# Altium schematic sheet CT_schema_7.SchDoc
size 301 x 247 mm
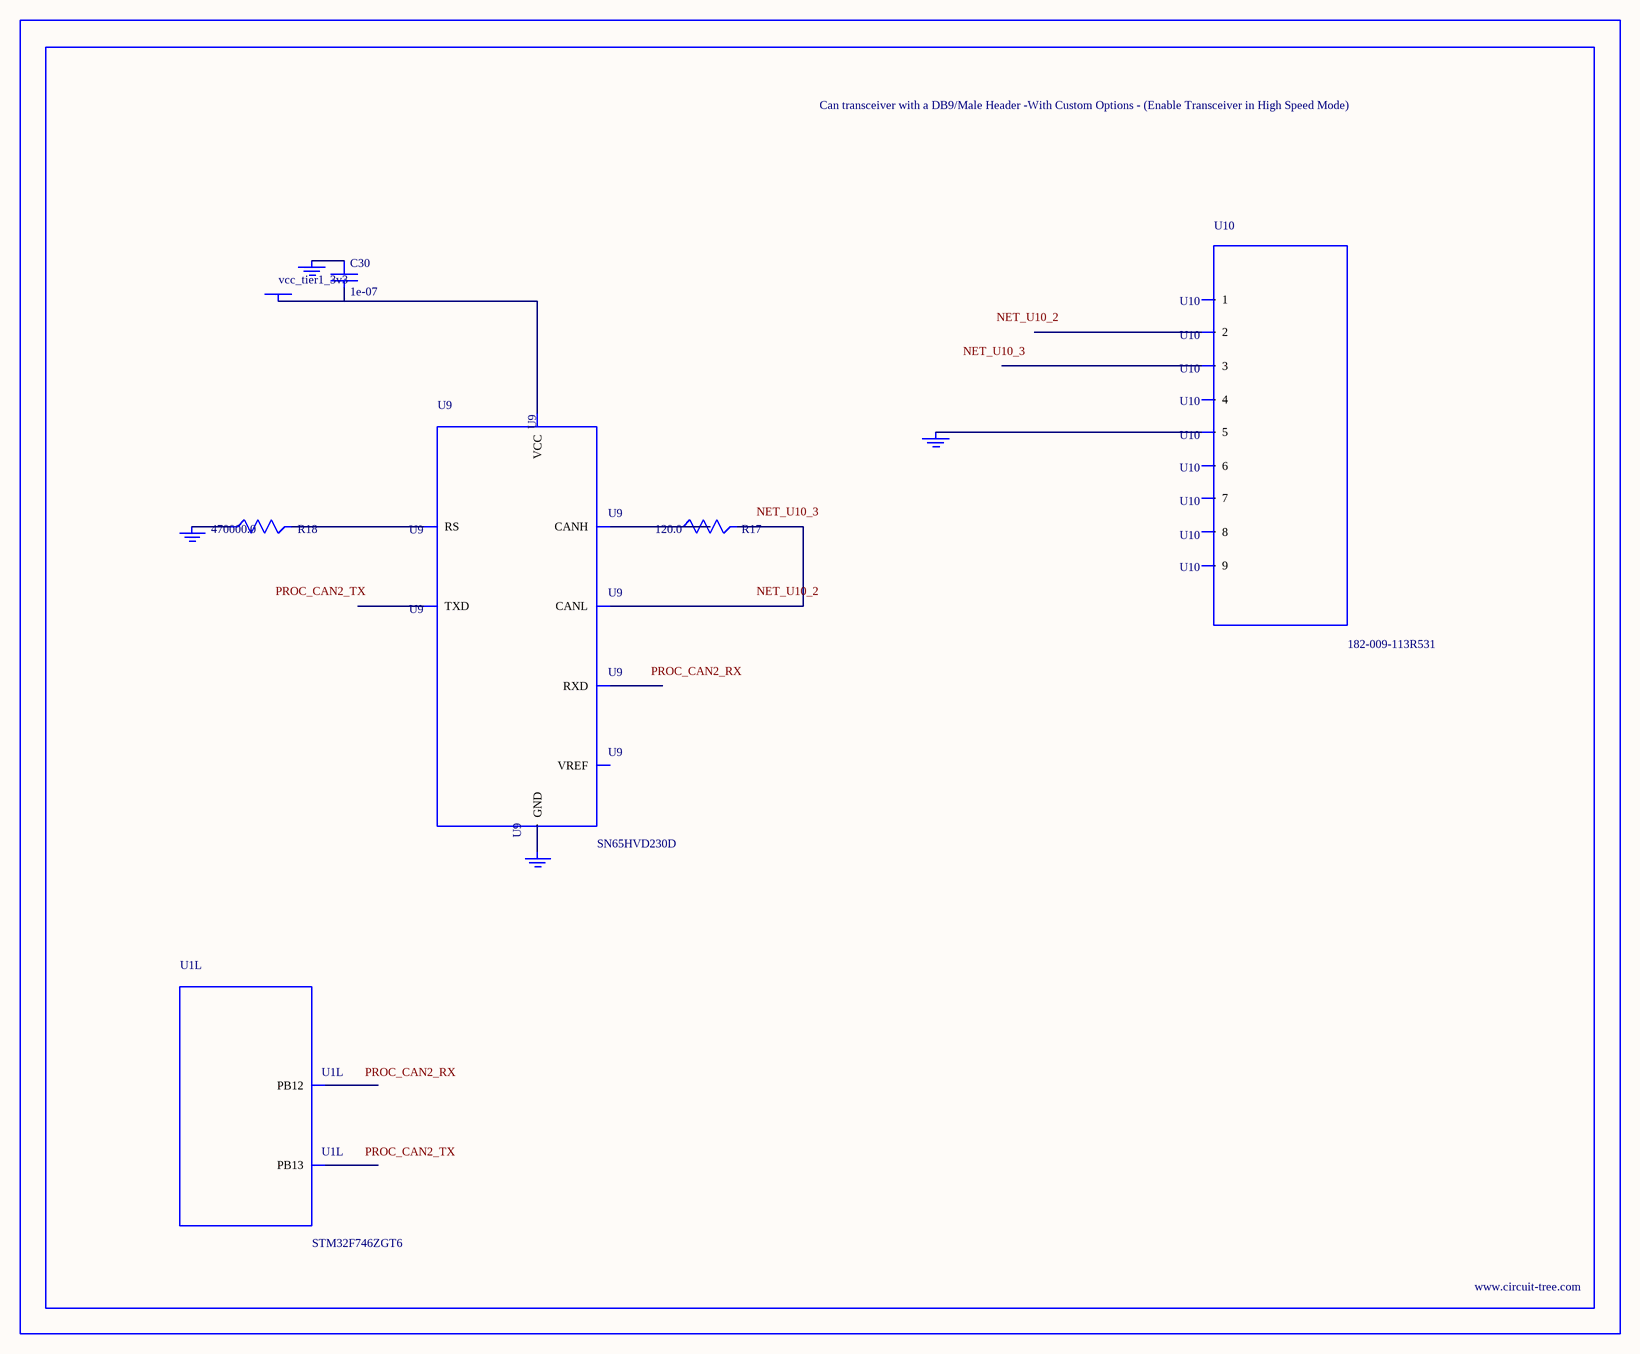
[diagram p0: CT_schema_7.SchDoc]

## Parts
BORDER6  (no value)
C30  1e-07  [C0402]
GND_INSTANCE_6_0  (no value)
GND_INSTANCE_6_1  (no value)
GND_INSTANCE_6_2  (no value)
GND_INSTANCE_6_3  (no value)
POWER_INSTANCE_6_0  vcc_tier1_3v3
R17  120.0  [R0603]
R18  470000.0  [R0603]
U1  STM32F746ZGT6  [LQFP144]  (part L of 12)
U9  SN65HVD230D  [SOIC-8]
U10  182-009-113R531  [182-009-MALE]

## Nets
NetC30_1: C30.1 GND_INSTANCE_6_0.0(GND)
NetC30_2: C30.2 POWER_INSTANCE_6_0.0(PWR) U9.3(VCC)
NetGND_INSTANCE_6_1_0: GND_INSTANCE_6_1.0(GND) R18.1
NetGND_INSTANCE_6_2_0: GND_INSTANCE_6_2.0(GND) U9.2(GND)
NetGND_INSTANCE_6_3_0: GND_INSTANCE_6_3.0(GND) U10.5
NetR17_1: R17.1 U9.7(CANH)
NetR17_2: R17.2 U9.6(CANL)
NetR18_2: R18.2 U9.8(RS)

Not connected (* = marked no-connect by the designer): U1 73(PB12) 74(PB13); U9 1(TXD) 4(RXD) 5(VREF); U10 1 2 3 4 6 7 8 9

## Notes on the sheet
- Labels drawn without touching a wire or pin: NET_U10_2, NET_U10_3, PROC_CAN2_RX, PROC_CAN2_TX

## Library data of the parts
BORDER6 = BORDER_PAGE6
C30 = C0402C104K3RACTU
GND_INSTANCE_6_0-GND_INSTANCE_6_3 = GND
POWER_INSTANCE_6_0 = PWR
R17 = RC0603JR-07120RL
R18 = RC0603JR-07470KL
